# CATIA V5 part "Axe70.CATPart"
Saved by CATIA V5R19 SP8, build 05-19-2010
Part number: Axe70
Bounding box of the stored display mesh (mm): x 0 to 70, y -15 to 15, z -15 to 15
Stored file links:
  J:\Travail\2e année\IAO\Projet\Axe70.CATPart
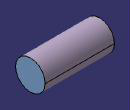
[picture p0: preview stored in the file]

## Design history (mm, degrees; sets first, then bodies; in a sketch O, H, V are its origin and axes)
Body1 (main body)
  Sketch1 on yz-plane, origin (0, 0, 0), H (0, 1, 0), V (0, 0, 1)
    circle A1 centre (0, 0) radius 15
    radius A1 = 15
  Pad1: profile Sketch1, direction (1, 0, 0), length 70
